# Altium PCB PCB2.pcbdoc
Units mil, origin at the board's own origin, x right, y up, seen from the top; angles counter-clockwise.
Board outline 1267.6 x 1521.5 mil, 2 copper layers (Top Layer, Bottom Layer), stack 62.2 mil thick; 12 components, 8 nets, 63 pads, 13 vias.
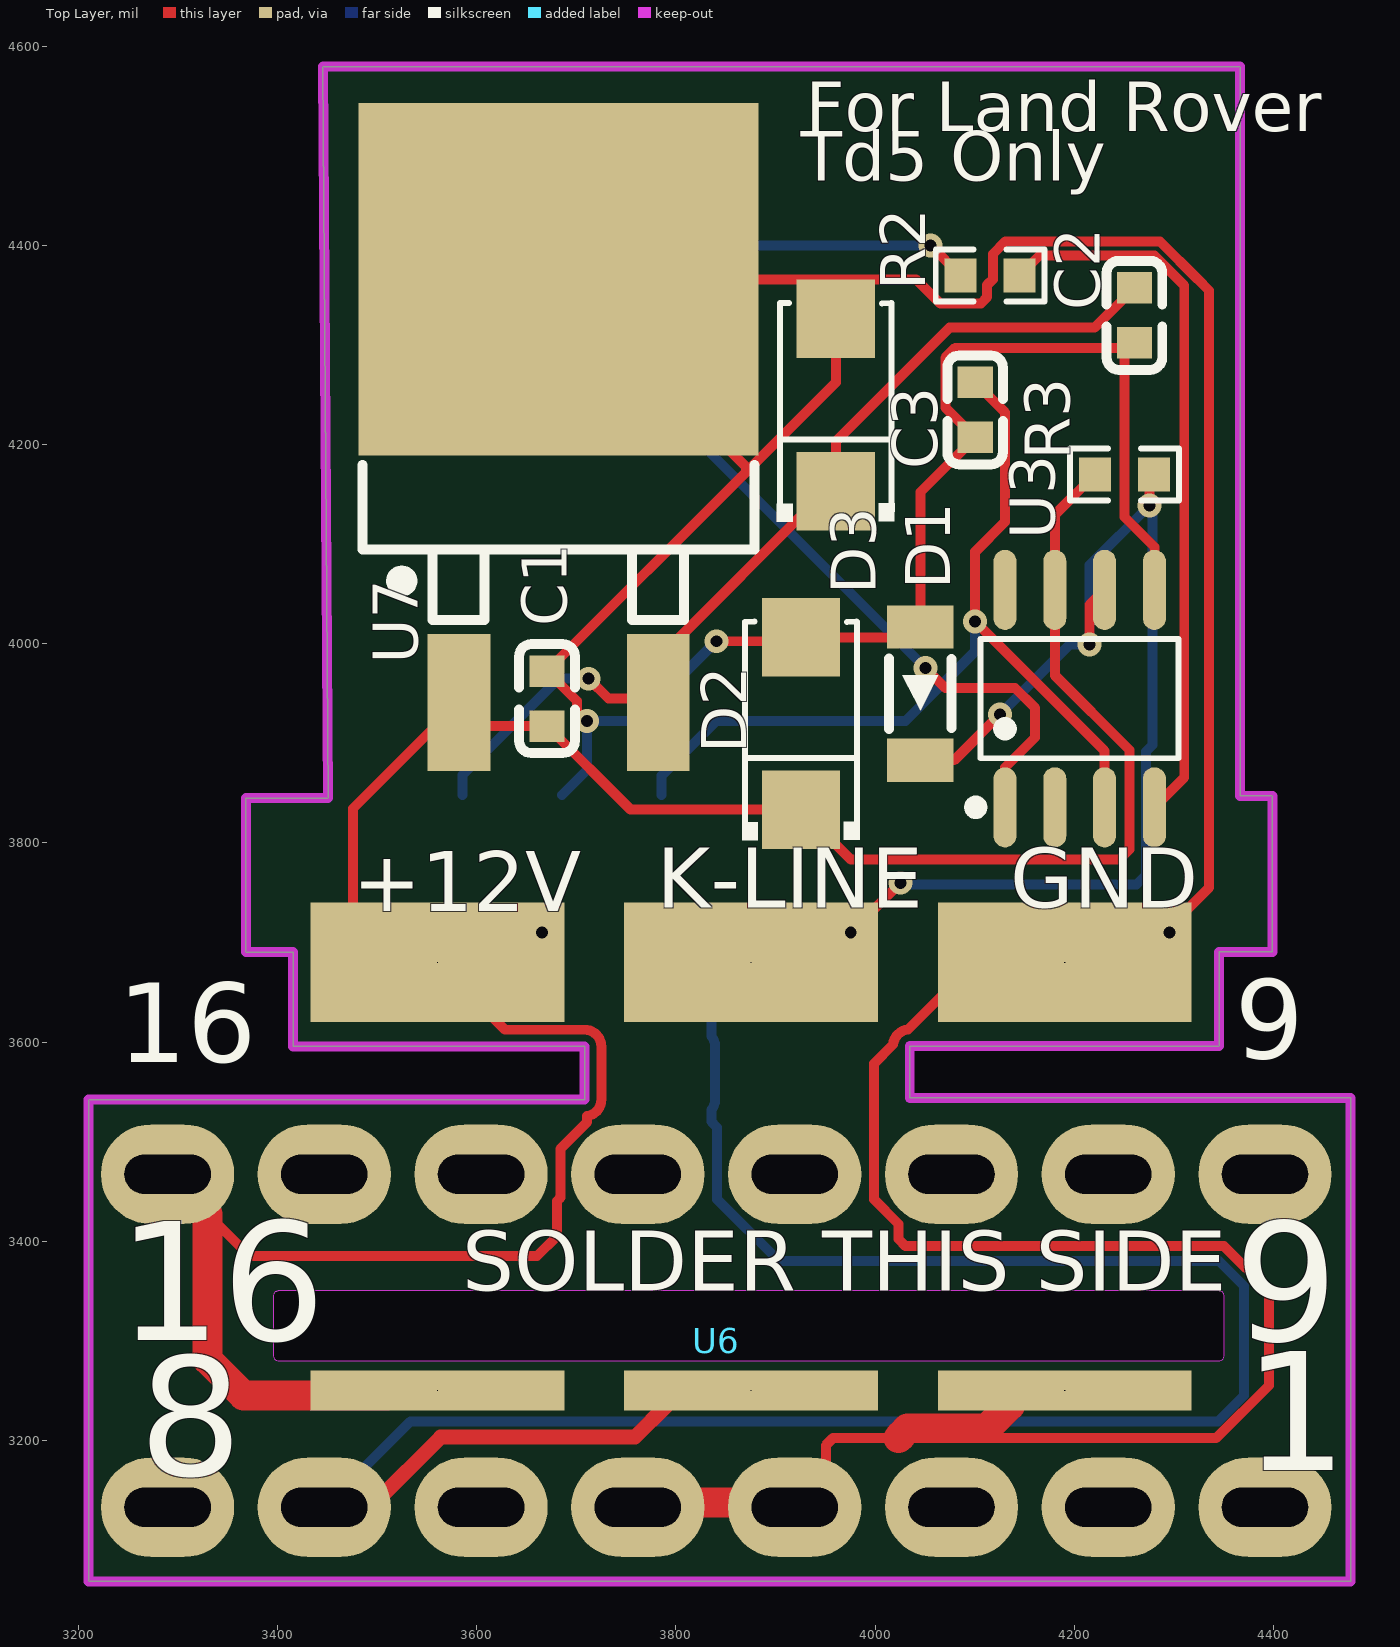
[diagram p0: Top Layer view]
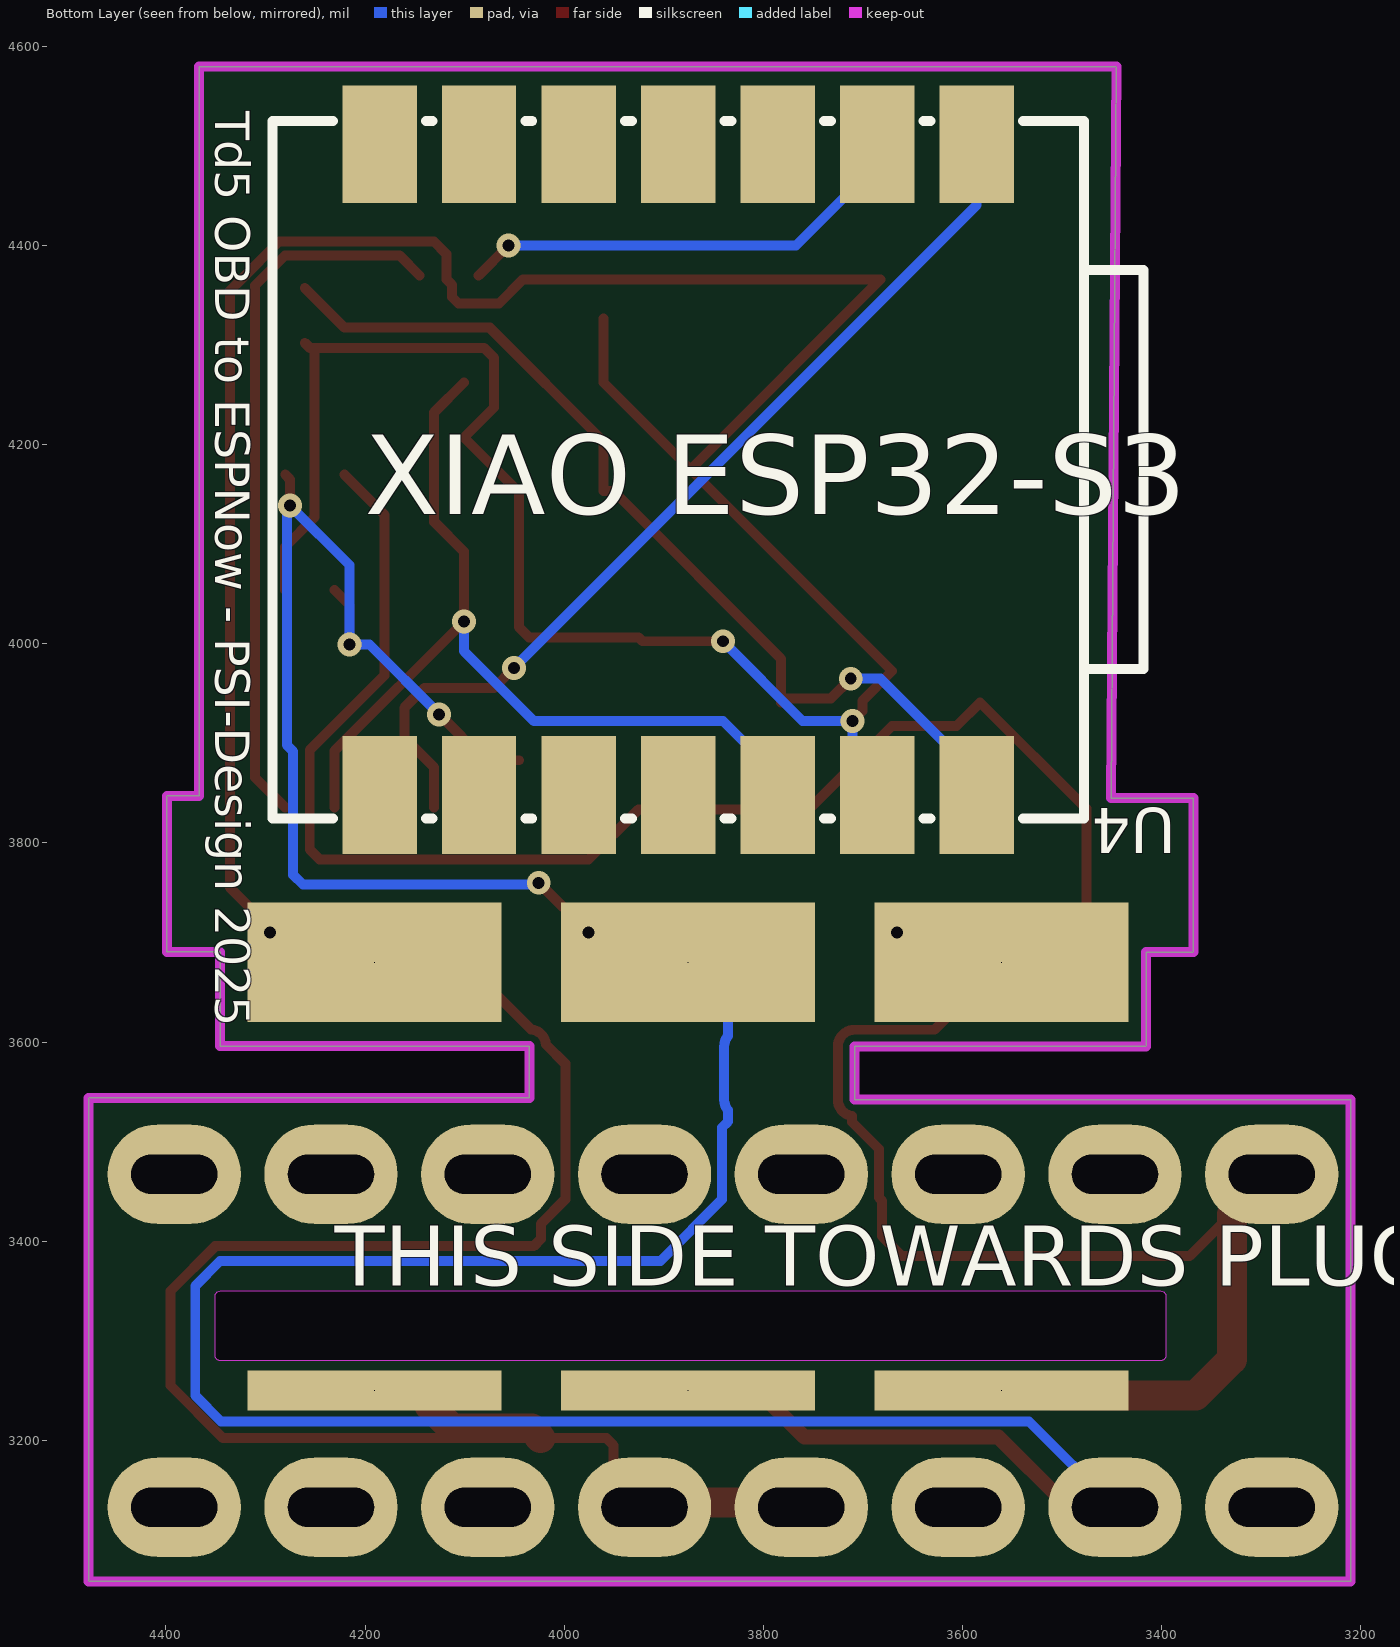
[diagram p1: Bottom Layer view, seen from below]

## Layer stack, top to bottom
Top Solder Mask Layer: solder mask 0.4, Dk 3.3
Top Layer: signal copper 1.4
Dielectric1: surface 59.4, FR4, Dk 4.5
Bottom Layer: signal copper 1.4
Bottom Solder Mask Layer: solder mask 0.4, Dk 3.3

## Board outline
3210.1,3058.3 4477.7,3058.3 4477.7,3543.9 4034.9,3543.9 4034.9,3595.9 4345.6,3595.9 4345.6,3690.6 4399.2,3690.6 4399.2,3847.2 4366.8,3847.2 4366.8,4579.8 3445.3,4579.8 3450.6,3845 3368.1,3845 3368.1,3690.3 3415.6,3690.3 3415.6,3595.6 3708.3,3595.6 3708.3,3542.2 3210.1,3542.2
cut-out: 3400.6,3350 ccw(c3400.6,3345) 3395.6,3345 3395.6,3285 ccw(c3400.6,3285) 3400.6,3280 4345.6,3280 ccw(c4345.6,3285) 4350.6,3285 4350.6,3345 ccw(c4345.6,3345) 4345.6,3350

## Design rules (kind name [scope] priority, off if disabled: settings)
BoardOutlineClearance copperThickness1oz [All] p0: genericclearance=10 ignorepadtopadclearanceinfootprint=FALSE except(0: Arc-SplitContinuation Track-SplitContinuation SMDPad-SplitContinuation THPad-SplitContinuation Via-SplitContinuation Fill-SplitContinuation Poly-SplitContinuation Region-SplitContinuation Text-SplitContinuation)
BoardOutlineClearance copperThickness2oz [All] p0: genericclearance=10 ignorepadtopadclearanceinfootprint=FALSE except(0: Arc-SplitContinuation Track-SplitContinuation SMDPad-SplitContinuation THPad-SplitContinuation Via-SplitContinuation Fill-SplitContinuation Poly-SplitContinuation Region-SplitContinuation Text-SplitContinuation)
BoardOutlineClearance Plane_innerPlane [All] p0: genericclearance=10 ignorepadtopadclearanceinfootprint=FALSE except(0: Arc-SplitContinuation Track-SplitContinuation SMDPad-SplitContinuation THPad-SplitContinuation Via-SplitContinuation Fill-SplitContinuation Poly-SplitContinuation Region-SplitContinuation Text-SplitContinuation)
BoardOutlineClearance Copper_copperRegion [All] p0: genericclearance=10 ignorepadtopadclearanceinfootprint=FALSE except(0: Arc-SplitContinuation Track-SplitContinuation SMDPad-SplitContinuation THPad-SplitContinuation Via-SplitContinuation Fill-SplitContinuation Poly-SplitContinuation Region-SplitContinuation Text-SplitContinuation)
BoardOutlineClearance otherClearance [All] p0: genericclearance=10 ignorepadtopadclearanceinfootprint=FALSE except(0: Arc-SplitContinuation Track-SplitContinuation SMDPad-SplitContinuation THPad-SplitContinuation Via-SplitContinuation Fill-SplitContinuation Poly-SplitContinuation Region-SplitContinuation Text-SplitContinuation)
Clearance copperThickness1oz [All] p1: gap=7 ignorepadtopadclearanceinfootprint=FALSE
Clearance copperThickness2oz [All] p1: gap=7 ignorepadtopadclearanceinfootprint=FALSE
Clearance Plane_innerPlane [All] p1: gap=7 ignorepadtopadclearanceinfootprint=FALSE
Clearance Copper_copperRegion [All] p1: gap=7 ignorepadtopadclearanceinfootprint=FALSE
Clearance otherClearance [All] p1: gap=7 ignorepadtopadclearanceinfootprint=FALSE
DiffPairsRouting differentialPair [All] p1: maxuncoupledlength=10 minlimit=6 maxlimit=Infinity mostfreqgap=6 toplayer_minwidth=5 toplayer_prefwidth=10 toplayer_maxwidth=100 bottomlayer_minwidth=5 bottomlayer_prefwidth=10 bottomlayer_maxwidth=100
PasteMaskExpansion pasteMaskExpansion [All] p1: expansion=0
PlaneConnect innerPlane [All] p1: planeconnectstyle=Relief reliefexpansion=20 reliefentries=4 reliefconductorwidth=10 reliefairgap=10
PolygonConnect copperRegion [All] p1: connectstyle=Relief reliefentries=4 reliefconductorwidth=10 polygonreliefangle="90 Angle" airgapwidth=10
RoutingVias viaSize [All] p1: viastyle="Through Hole" holewidth=12.0078 minholewidth=11.811 maxholewidth=248.0314 width=12.0078 minwidth=11.811 maxwidth=248.0314
SolderMaskExpansion solderMaskExpansion [IsVia] p1: useseparateexpansions=TRUE expansion=-1000 expansionbottom=-1000
SolderMaskExpansion solderMaskExpansion [All] p2: useseparateexpansions=TRUE expansion=2 expansionbottom=2
Width copperThickness1oz [All] p1: maxlimit=100 minlimit=5 preferedwidth=10
Width copperThickness2oz [All] p1: maxlimit=100 minlimit=8 preferedwidth=10

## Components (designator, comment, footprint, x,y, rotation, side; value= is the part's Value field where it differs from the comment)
C1 "330nF" C0603 3670.6,3945 r270 top
C2 "330nF" C0603 4260.6,4330 r90 top
C3 "330nF" C0603 4100.6,4235 r90 top
D1 "ZMM27V" LL-34_L3.5-W1.5-RD 4045.6,3950 r90 top
D2 "SS34" SMA_L4.3-W2.6-LS5.2-RD 3925.6,3920 r90 top
D3 "SS34" SMA_L4.3-W2.6-LS5.2-RD 3960.6,4240 r90 top
R2 "1kΩ" R0603 4115.6,4370 r0 top
R3 "510R" R0603 4250.6,4170 r0 top
U3 "E-L9637D013TR" SOIC-8_L4.9-W3.9-P1.27-LS6.0-BL 4205.6,3945 r0 top
U4 "XIAO ESP32S3" COMM-SMD_KQ-2801_V106 3885.6,4175 r0 bottom
U6 "OBD2" OBD2 3840.6,3300 r0 top
U7 "L7805ABD2T-TR" TO-263-2_L10.0-W9.2-P5.08-LS15.3-TL-CW 3682.2,4153.7 r90 top

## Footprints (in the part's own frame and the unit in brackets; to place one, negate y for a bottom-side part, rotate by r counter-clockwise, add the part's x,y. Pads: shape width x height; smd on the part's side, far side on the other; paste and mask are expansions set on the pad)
C0603 [mil]
  rect 31.5x35.4 smd: 1(-27.6,0) 2(27.6,0)
  silkscreen extent -55,-28 55,28
COMM-SMD_KQ-2801_V106 [mil]
  rect 74.8x118.1 smd: 1(-300,-326.8) 2(-200,-326.8) 3(-100,-326.8) 4(0,-326.8) 5(100,-326.8) 6(200,-326.8) 7(299.9,-326.8) 8(299.9,326.8) 9(200,326.8) 10(100,326.8) 11(0,326.8) 12(-100,326.8) 13(-200,326.8) 14(-300,326.8)
  silkscreen extent -467,-350 407,350
LL-34_L3.5-W1.5-RD [mil]
  rect 43.3x66.9 smd: 1(-66.9,0) 2(66.9,0)
  silkscreen extent -35,-31 35,32
OBD2 [mm]
  oval 3.401x2.54 hole 1.001 slot 2.2 at 0 deg paste+0 mask+0.102: 1(13.998,-4.249) 2(10,-4.249) 3(5.999,-4.249) 4(1.999,-4.249) 5(-2.002,-4.249) 6(-6.002,-4.249) 7(-10.003,-4.249) 8(-14,-4.249) 9(13.998,4.249) 10(10,4.249) 11(5.999,4.249) 12(1.999,4.249) 13(-2.002,4.249) 14(-6.002,4.249) 15(-10.003,4.249) 16(-14,4.249)
R0603 [mil]
  rect 31.8x34 smd paste-3937 mask+2: 1(-29.7,0) 2(29.6,0)
  silkscreen extent -55,-26 54,26
SMA_L4.3-W2.6-LS5.2-RD [mil]
  rect 78.7x78.7 smd: 1(-86.6,0) 2(86.6,0)
  silkscreen extent -117,-59 102,59
SOIC-8_L4.9-W3.9-P1.27-LS6.0-BL [mil]
  oval 23.1x80.5 smd: 1(-75,-109.2) 2(-25,-109.2) 3(25,-109.2) 4(75,-109.2) 5(75,109.2) 6(25,109.2) 7(-25,109.2) 8(-75,109.2)
  silkscreen extent -110,-115 99,60
TO-263-2_L10.0-W9.2-P5.08-LS15.3-TL-CW [mil]
  rect 137.8x63 smd: 1(-212.5,100) 3(-212.5,-100)
  rect 354.3x401.6 smd: 2(212.5,0)
  silkscreen extent -130,-197 26,197

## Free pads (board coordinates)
  rect 255x40 hole 0.1: 1(3560.6,3250) 4(4190.6,3250) 5(3875.6,3250)
  rect 255x120 hole 0.1: 1(3560.6,3680) 2(3875.6,3680) 3(4190.6,3680)

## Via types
v1: diameter 24, hole 12, Top Layer to Bottom Layer, 13 vias

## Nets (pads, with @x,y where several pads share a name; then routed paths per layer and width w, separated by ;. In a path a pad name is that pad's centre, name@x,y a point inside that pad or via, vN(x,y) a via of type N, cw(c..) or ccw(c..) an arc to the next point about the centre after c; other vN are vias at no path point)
12V: C1.2 D2.1 pad.1 R3.1 U3.7 U6.16 U7.1 | length 2634.9
  Top Layer w10: U6.16 3329.4,3427.3 3371.7,3385 3660.6,3385 3680.6,3405 3680.6,3440.4 3683.9,3443.7 3683.9,3492.6 3710.9,3519.6 3710.9,3525.6 ccw(c3708.3,3542.2) 3725.1,3542.2 3725.1,3595.6 ccw(c3708.3,3595.6) 3708.3,3612.4 3628.2,3612.4 pad.1@3560.6,3680 ; pad.1@3475.6,3705 3475.6,3834.6 U7.1 3605.9,3917.4 C1.2 3754.6,3833.4 D2.1 3975.6,3783.4 4245.6,3783.4 4255.6,3793.4 4255.6,3893.4 4180.6,3968.4 U3.7 4180.6,4129.7 R3.1
  Top Layer w30: U6.16@3329.4,3427.3 3329.4,3281.2 3365.6,3245 pad.1@3509.6,3245
  other v1: 3665.6,3710
$1N635: R2.2 U3.4 | length 722.7
  Top Layer w10: R2.2 4165.2,4390 4280.6,4390 4310.6,4360 4310.6,3865.8 U3.4
$1N1067: C2.2 D3.1 U4.14 U7.3 | length 971
  Top Layer w10: v1(3712.2,3965) 3732.2,3945 U7.3@3782.2,3945 ; U7.3 U7.3@3782.2,3945 ; C2.2 4220.6,4317.6 4074.7,4317.6 3960.6,4203.4 D3.1 3950.6,4153.4 3782.2,3985 U7.3@3782.2,3945
  Bottom Layer w10: U4.14 3585.6,3868.4 3682.2,3965 v1(3712.2,3965)
$1N1121: R2.1 U4.2 | length 466.6
  Top Layer w10: v1(4055.9,4400) R2.1
  Bottom Layer w10: U4.2 3687.3,4500 3687.3,4480 3767.3,4400 v1(4055.9,4400)
$1N1128: U3.1 U4.1 | length 957.6
  Top Layer w10: v1(4050.6,3975.8) 4070.6,3955.8 4140.6,3955.8 4160.6,3935.8 4160.6,3905.8 4130.6,3875.8 U3.1
  Bottom Layer w10: U4.1 3585.6,4440.8 v1(4050.6,3975.8)
$1N1153: C3.2 U3.3 U4.12 | length 921.7
  Top Layer w10: C3.2 4130.6,4232.6 4130.6,4122.6 4100.6,4092.6 v1(4100.6,4022.6) 4230.6,3892.6 U3.3
  Bottom Layer w10: U4.12 3785.6,3867.6 3840.6,3922.6 4030.6,3922.6 4100.6,3992.6 v1(4100.6,4022.6)
GND: C1.1 C2.1 C3.1 D1.2 D2.2 D3.2 pad.3 pad.4 U3.5 U4.13 U6.4 U6.5 U7.2 | length 5156
  Top Layer w10: v1(3710.6,3922.6) 3700.6,3932.6 3700.6,3942.6 C1.1 3870.6,4172.6 ; v1(3840.6,4002.6) 3921.5,4002.6 D2.2 4035.2,4006.6 D1.2 4045.6,4152.4 C3.1 4070.6,4237.4 4070.6,4287.4 4080.6,4297.4 C2.1@4250.6,4297.4 ; U6.4 3924.3,3137.7 3950.6,3163.9 3950.6,3195 3957.6,3202.1 4023.7,3202.1 4342.6,3202.1 4395.6,3255 4395.6,3350 4350.6,3395 4030.6,3395 4023.5,3402.1 4023.5,3417.4 3998.9,3442.1 3998.9,3578.3 4018.2,3597.6 ; D3.2 3960.6,4262.6 3870.6,4172.6 ; 4018.19,3597.66 cw(c4034.9,3595.9) 4033.14,3612.61 ; 4033.1,3612.6 4100.6,3680 pad.3 ; C2.1 4255.6,4297.4 C2.1@4250.6,4297.4 ; U3.5 4280.6,4097.4 4250.6,4127.4 C2.1@4250.6,4297.4 ; pad.3@4300.6,3720 4335.6,3755 4335.6,4355 4324.3,4366.2 4324.2,4366.2 4286.4,4404 4130.8,4404 4118.4,4391.6 4118.4,4366.2 4112.7,4360.6 4112.7,4348.4 4106.3,4342 4065.5,4342 4041.3,4366.2 U7.2 3870.6,4177.8 3870.6,4172.6
  Top Layer w30: U6.5 3766.8,3137.7 U6.4@3924.3,3137.7 ; 4023.7,3202.1 4025.6,3203.9 4025.6,3205 4032.6,3212.1 4112.6,3212.1 pad.4@4135.6,3235
  Bottom Layer w10: U4.13 3710.6,3873.2 v1(3710.6,3922.6) 3760.6,3922.6 v1(3840.6,4002.6)
  other v1: 4295.7,3710
K-LINE: D1.1 pad.2 pad.5 R3.2 U3.6 U6.7 | length 3514.2
  Top Layer w10: pad.2@3925.6,3710 v1(3975.6,3710) v1(4025.6,3760) ; D1.1 4079.5,3883.1 v1(4125.6,3929.2) ; v1(4215.6,3999.2) 4215.6,4039.2 U3.6 ; v1(4275.6,4139.1) 4275.6,4165.3 R3.2
  Top Layer w15: U6.7@3446.9,3132.7 3451.9,3137.7 3498.2,3137.7 3563.7,3203.2 3758.7,3203.2 pad.5@3790.6,3235
  Bottom Layer w10: U6.7@3446.9,3132.7 3533.2,3219 4344.6,3219 4370.6,3245 4370.6,3355 4345.6,3380 3903.4,3380 3841.4,3442.1 3841.4,3514.2 3835.6,3520 3835.6,3531.7 ; 3835.59,3531.67 ccw(c3822.5,3542.2) 3839.3,3542.2 3839.3,3595.6 ccw(c3822.5,3595.6) 3835.59,3606.13 ; 3835.6,3606.1 3835.6,3640 pad.2 ; v1(4025.6,3760) 4027.4,3758.2 4262.5,3758.2 4272.2,3767.9 4272.2,3891.8 4278.6,3898.3 4278.6,4136.1 v1(4275.6,4139.1) 4215.6,4079.2 v1(4215.6,3999.2) 4195.6,3999.2 v1(4125.6,3929.2)
pads on no net: U3.2 U3.8 U4.3 U4.4 U4.5 U4.6 U4.7 U4.8 U4.9 U4.10 U4.11 U6.1 U6.2 U6.3 U6.6 U6.8 U6.9 U6.10 U6.11 U6.12 U6.13 U6.14 U6.15

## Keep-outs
Board Outline Layer:
  region: 3400.6,3350 ccw(c3400.6,3345) 3395.6,3345 3395.6,3285 ccw(c3400.6,3285) 3400.6,3280 4345.6,3280 ccw(c4345.6,3285) 4350.6,3285 4350.6,3345 ccw(c4345.6,3345) 4345.6,3350
  region: 3400.6,3350 ccw(c3400.6,3345) 3395.6,3345 3395.6,3285 ccw(c3400.6,3285) 3400.6,3280 4345.6,3280 ccw(c4345.6,3285) 4350.6,3285 4350.6,3345 ccw(c4345.6,3345) 4345.6,3350
  lines w0.1: 3395.6,3285 3395.6,3345 cw(c3400.6,3345) 3400.6,3350 4345.6,3350 cw(c4345.6,3345) 4350.6,3345 4350.6,3285 cw(c4345.6,3285) 4345.6,3280 3400.6,3280 cw(c3400.6,3285) 3395.6,3285
  lines w10: 3210.1,3058.3 4477.7,3058.3 4477.7,3543.9 4034.9,3543.9 4034.9,3595.9 4345.6,3595.9 4345.6,3690.6 4399.2,3690.6 4399.2,3847.2 4366.8,3847.2 4366.8,4579.8 3445.3,4579.8 3450.6,3845 3368.1,3845 3368.1,3690.3 3415.6,3690.3 3415.6,3595.6 3708.3,3595.6 3708.3,3542.2 3210.1,3542.2 3210.1,3058.3

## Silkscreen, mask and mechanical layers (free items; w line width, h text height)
Top Silkscreen Layer:
  text "For Land Rover" at 3930.6,4515 h50
  text "Td5 Only" at 3925.6,4465 h50
  text "K-LINE" at 3780.6,3735 h60
  text "GND" at 4135.6,3735 h60
  text "+12V" at 3475.6,3731.6 h60
  text "SOLDER THIS SIDE" at 3585.6,3350 h60
  text "16" at 3239.3,3300.3 h120
  text "9" at 4360.6,3300 h120
  text "1" at 4370.6,3170 h120
  text "8" at 3260.6,3165 h120
Bottom Silkscreen Layer:
  text "Td5 OBD to ESPNow - PSI-Design 2025" at 4350.6,4535 h35 r90
  text "XIAO ESP32-S3" at 4200.6,4130 h80
  text "THIS SIDE TOWARDS PLUG" at 4230.6,3355 h60
Mechanical Layer:
  lines w0.1: 3395.6,3285 3395.6,3345 cw(c3400.6,3345) 3400.6,3350 4345.6,3350 cw(c4345.6,3345) 4350.6,3345 4350.6,3285 cw(c4345.6,3285) 4345.6,3280 3400.6,3280 cw(c3400.6,3285) 3395.6,3285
